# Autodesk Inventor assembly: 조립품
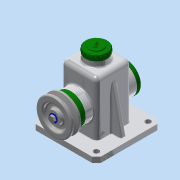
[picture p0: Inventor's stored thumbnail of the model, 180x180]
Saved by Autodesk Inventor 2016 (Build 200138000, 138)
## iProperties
Created: 2018-11
Part Number: 조립품
Material: 일반
Document SubType Name: Assembly
Designer: user
Author: user
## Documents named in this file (14)
- C:\Users\user\Desktop\481121V1012\조립품.iam
- C:\Users\user\Desktop\481121V1012\V-벨트풀리.ipt
- C:\Users\user\Desktop\481121V1012\뒤커버.ipt
- C:\Users\user\Desktop\481121V1012\멈춤링 15 x 1.ipt
- C:\Users\user\Desktop\481121V1012\베어링 15 x 35 x 11.ipt
- C:\Users\user\Desktop\481121V1012\본체.ipt
- C:\Users\user\Desktop\481121V1012\볼트 M4 x 10.ipt
- C:\Users\user\Desktop\481121V1012\볼트 M6 x 12.ipt
- C:\Users\user\Desktop\481121V1012\상부캡.ipt
- C:\Users\user\Desktop\481121V1012\앞커버.ipt
- C:\Users\user\Desktop\481121V1012\오일실 15 25 7.ipt
- C:\Users\user\Desktop\481121V1012\와셔.ipt
- C:\Users\user\Desktop\481121V1012\축.ipt
- C:\Users\user\Desktop\481121V1012\키 5 x 5 x 14.ipt
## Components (1 placed, 1 different names)
1. V-벨트풀리:1
